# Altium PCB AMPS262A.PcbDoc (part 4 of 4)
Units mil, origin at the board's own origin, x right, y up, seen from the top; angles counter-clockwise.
Board outline 5314.96 x 4803.15 mil, 4 copper layers (Top Layer, GND, Copper Layer 3, Bottom Layer), stack 79.28 mil thick; 324 components, 156 nets, 943 pads, 1411 vias.
Unrouted connection lines stored in the file: 130.
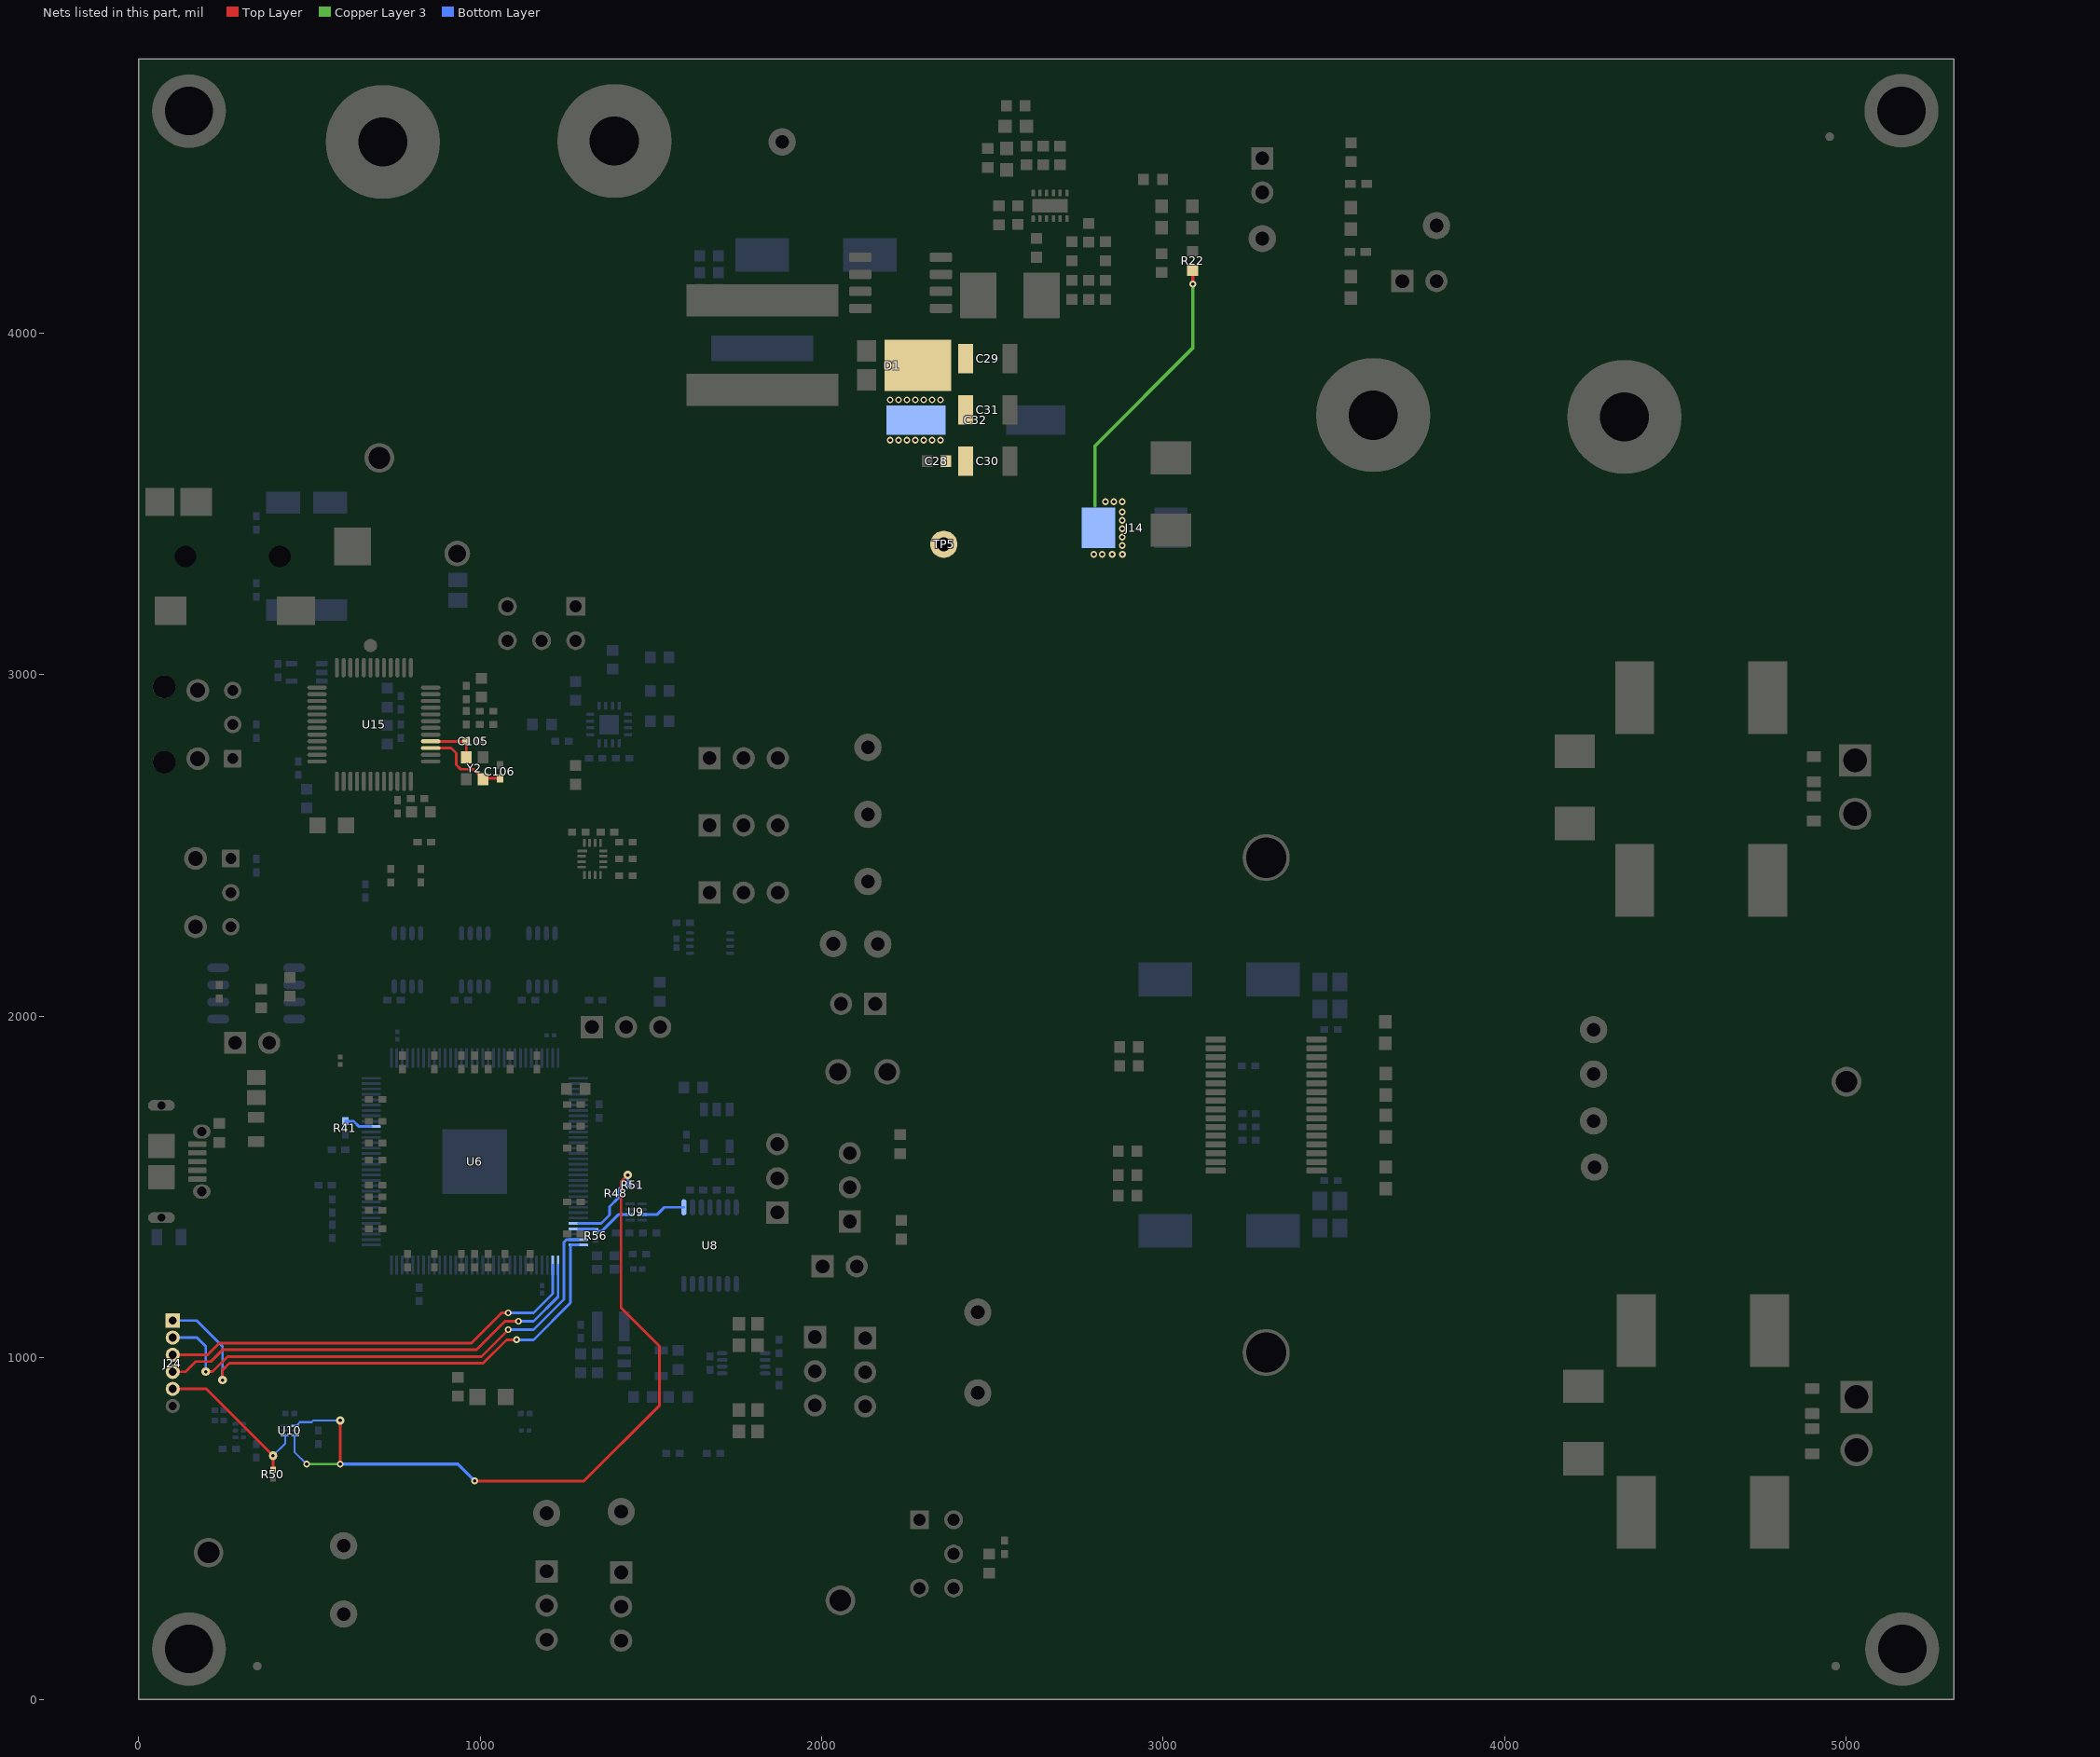
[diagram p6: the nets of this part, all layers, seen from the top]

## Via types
v1: diameter 20, hole 10, Top Layer to Bottom Layer, tented both sides, 1299 vias
v2: diameter 25, hole 10, Top Layer to Bottom Layer, tented both sides, 87 vias
v3: diameter 23.62, hole 11.81, Top Layer to Bottom Layer, 12 vias
v4: diameter 19.68, hole 7.87, Top Layer to Bottom Layer, 7 vias
v5: diameter 20, hole 10, Top Layer to Bottom Layer, 6 vias

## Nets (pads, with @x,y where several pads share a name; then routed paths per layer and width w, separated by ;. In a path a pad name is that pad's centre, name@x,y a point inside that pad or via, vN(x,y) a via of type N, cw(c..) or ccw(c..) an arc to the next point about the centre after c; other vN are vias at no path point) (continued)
VOUT_LM5155: C28.1 C29.1 C30.1 C31.1 C32.1 D1.3 J14.1 R22.2 TP5.1 | length 807.7
  Top Layer w9.84: v1(3086.32,4143.64) R22.2@3086.32,4184.09
  Copper Layer 3 w10: 2800,3495 2800,3670 3086.32,3956.32 v1(3086.32,4143.64)
  other v1: 2796.61,3352.5 2821.22,3352.5 2850.75,3352.5 2880.28,3352.5 2880,3378.29 2880,3402.89 2880,3427.5 2880,3452.11 2880,3476.71 2830.79,3506.24 2855.39,3506.24 2880,3506.24 2200.33,3686.6 2224.93,3686.6 2249.54,3686.6 2274.15,3686.6 2298.75,3686.6 2323.36,3686.6 2347.97,3686.6 2200.33,3804.71 2224.93,3804.71 2249.54,3804.71 2274.15,3804.71 2298.75,3804.71 2323.36,3804.71 2347.97,3804.71
X-24M: R56.2 U6.125 U9.2 | length 174.2
  Bottom Layer w7.87: U6.125@1287.4,1377.95 1331.89,1377.95 R56.2@1338.58,1371.26 1356.5,1371.26 1404.53,1419.29 U9.2@1438.98,1419.29
X-HS-EN: R41.1 U6.55 | length 82.3
  Bottom Layer w7.87: R41.1@605.32,1692.91 629.92,1692.91 645.67,1677.17 U6.55@681.1,1677.17
X-RSTN: R48.2 R51.2 U6.124 U10.4 U10.6 | length 2490.7
  Top Layer w7.87: v1(590.55,688.98) v2(590.55,816.93) ; v1(984.25,639.76) 1304.13,639.76 1525.59,861.22 1525.59,1033.46 1412.4,1146.65 1412.4,1515.75 v2(1432.09,1535.43)
  Copper Layer 3 w7.87: v1(492.13,688.98) v1(590.55,688.98)
  Bottom Layer w5.91: U10.6@456.3,773.62 456.3,724.8 v1(492.13,688.98) ; U10.4@461.61,801.18 472.44,812.01 506.89,812.01 511.81,816.93 v2(590.55,816.93)
  Bottom Layer w7.87: U6.124@1287.4,1393.7 1354.33,1393.7 1378.94,1418.31 1378.94,1442.91 1405.51,1469.49 1405.51,1478.15 R48.2@1408.66,1481.3 1407.48,1482.48 1407.48,1496.06 1417.32,1505.91 R51.2@1433.86,1505.91 1432.09,1507.68 v2(1432.09,1535.43)
  Bottom Layer w10: v1(590.55,688.98) 935.04,688.98 v1(984.25,639.76)
X-TCK: J24.1 U6.128 | length 1596.4
  Top Layer w7.87: v2(246.06,935.04) 246.06,964.57 265.75,984.25 1008.86,984.25 1077.76,1053.15 v1(1107.28,1053.15)
  Bottom Layer w7.87: J24.1@100,1109.25 170.28,1109.25 246.06,1033.46 v2(246.06,935.04) ; v1(1107.28,1053.15) 1156.5,1053.15 1264.76,1161.42 1264.76,1328.74 1266.73,1330.71 U6.128@1287.4,1330.71
X-TDI: J24.3 U6.2 | length 1270.3
  Top Layer w7.87: J24.3@100,1009.25 202.17,1009.25 236.22,1043.31 974.41,1043.31 1062.99,1131.89 v1(1082.68,1131.89)
  Bottom Layer w7.87: v1(1082.68,1131.89) 1156.5,1131.89 1212.6,1187.99 U6.2@1212.6,1271.65
X-TDO: J24.4 U6.1 | length 1311.9
  Top Layer w7.87: J24.4@100,959.25 137.4,959.25 167.32,989.17 211.61,989.17 246.06,1023.62 989.17,1023.62 1072.83,1107.28 v1(1112.2,1107.28)
  Bottom Layer w7.87: v1(1112.2,1107.28) 1156.5,1107.28 1228.35,1179.13 U6.1@1228.35,1271.65
X-TMS: J24.2 U6.127 | length 1535.1
  Top Layer w7.87: v2(196.85,959.65) 216.54,959.65 260.83,1003.94 1003.94,1003.94 v1(1082.68,1082.68)
  Bottom Layer w7.87: J24.2@100,1059.25 171.06,1059.25 196.85,1033.46 v2(196.85,959.65) v2@196.85,954.72 ; v1(1082.68,1082.68) 1156.5,1082.68 1245.08,1171.26 1245.08,1338.58 1252.95,1346.46 U6.127@1287.4,1346.46
X-TRSTN: J24.5 R50.2 U10.1 | length 563.9
  Top Layer w7.87: J24.5@100,909.25 198.03,909.25 v2(393.7,713.58) R50.2@393.7,674.21
  Bottom Layer w5.91: 429.53,749.41 v2(393.7,713.58) 429.53,749.41 ; 429.53,749.41 429.53,773.62 429.53,749.41
XIN/CLK: U8.1 U9.7 | length 131
  Bottom Layer w7.87: U9.7@1474.41,1419.29 1517.72,1419.29 1539.37,1440.94 U8.1@1596.46,1440.94
XTI: C106.1 U15.39 Y2.1 | length 262.6
  Top Layer w7.87: U15.39@855.32,2785.43 915.35,2785.43 930.12,2770.67 930.12,2736.22 942.91,2723.43 980.29,2723.43 1008.86,2694.85 Y2.1@1008.86,2693.9 1011.81,2696.85 C106.1@1058.07,2696.85
XTO: C105.1 U15.40 Y2.3 | length 150.6
  Top Layer w7.87: U15.40@855.32,2805.12 C105.1@959.65,2805.12 Y2.3@959.65,2758.86
pads on no net: FID1.1 FID2.1 FID3.1 FID4.1 FID5.1 FID6.1 H2. H3. H4. H5. J30.MH1 J30.MH2 R73.2 R74.2 S1.1 S1.3 S1.6 S2.1 S2.3 SH-J1.0 SH-J2.0 SH-J3.0 SH-J4.0 SH-J5.0 SH-J6.0 SH-J7.0 SH-J8.0 SH-J9.0 SH-J10.0 U3.7 U6.4 U6.5 U6.7 U6.8 U6.9 U6.10 U6.12 U6.15 U6.18 U6.20 U6.21 U6.22 U6.23 U6.25 U6.26 U6.28 U6.30 U6.31 U6.32 U6.33 U6.34 U6.35 U6.39 U6.40 U6.50 U6.51 U6.53 U6.54 U6.57 U6.58 U6.59 U6.61 U6.62 U6.65 U6.68 U6.69 U6.70 U6.71 U6.72 U6.74 U6.75 U6.76 U6.77 U6.79 U6.82 U6.84 U6.85 U6.86 U6.89 U6.90 U6.91 U6.93 U6.94 U6.95 U6.96 U6.97 U6.98 U6.99 U6.100 U6.106 U6.107 U6.108 U6.109 U6.112 U6.113 U6.114 U6.115 U6.117 U6.118 U6.119 U6.121 U6.122 U8.4 U8.8 U8.14 U9.6 U12. U12.4 U12.5 U14.4 U14.5 U15.2 U15.3 U15.4 U15.5 U15.6 U15.11 U15.12 U15.13 U15.14 U15.16 U15.28 U15.29 U15.30 U15.31 U15.32 U15.35 U15.37 U16.3 U17.3 U18.1 U19.3 U20.2 U20.3 U21.4 U21.11 U21.17@1377.95,2854.33
copper on no net:
  other v1: 1421,1590.19

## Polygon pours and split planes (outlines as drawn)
VOUT_LM5155 on Copper Layer 3 "COPPER_LAYER_3_VOUT_LM5155_P083" (solid, remove dead copper, pour order 83): 2180.64,3833.86 2356.14,3833.86 2375,3815 2375,3535 2395,3525 2885,3525 2910,3500 2910,3334.55 2310,3334.55 2180,3407.5 2180.64,3165.64 2180,3834.5
GND on Copper Layer 3 "COPPER_LAYER_3_GND_P133" (solid, remove dead copper, pour order 133): 0,4305.65 494.35,4800 4647.5,4800 5315,4132.5 5315,510 5307.5,510 4800,2.5 512.5,2.5 512.5,12.5 210,315 0,315 0,4302.5 -2.5,4305
5V-U3 on Copper Layer 3 "COPPER_LAYER_3_5V-U3_P000" (solid, remove dead copper, pour order 0): 187.01,2155.51 147.64,2116.14 147.64,1865.16 310.87,1865.16 322.5,1883.55 322.5,2118.44 285.43,2155.51
PVDD_5828 on Copper Layer 3 "COPPER_LAYER_3_PVDD_5828_P085" (solid, remove dead copper, pour order 85): 3452.5,2787.5 2940,3222.5 2940,3365 3100,3365 3623.38,2922.41 3623.38,2821.1
VIN on Copper Layer 3 "Copper Layer 3-VIN" (solid, pour order 77): 1606.19,4745 1960.59,4745 2015,4690.59 2014.37,4689.96 2014.37,4279.37 2000,4265 1630,4265 1606.19,4288.81
PVDD_5828 on Copper Layer 3 "COPPER_LAYER_3_PVDD_5828_P064" (solid, remove dead copper, pour order 64): 3451.28,2821.1 3451.28,2488.63 3181.28,2218.63 3181.28,2052.1 3317.28,1916.1 3317.28,1548.56 3181.28,1412.56 3181.28,1295.56 3197.28,1279.56 3567.85,1279.56 3587.77,1299.48 3587.77,2247.64 3623.38,2283.25 3623.38,2821.1
3.3V on Copper Layer 3 "COPPER_LAYER_3_3.3V_P004" (solid, remove dead copper, pour order 4): 831.69,1825.79 639.76,2017.72 639.76,2312.99 984.25,2657.48 984.25,3041.34 964.57,3061.02 964.57,3179.13 944.88,3198.82 925.2,3198.82 905.51,3179.13 905.51,3061.02 885.83,3041.34 836.61,3041.34 836.61,2908.46 733.27,2805.12 733.27,2750.98 472.44,2490.16 472.44,2249.02 388.78,2165.35 388.78,2071.85 723.42,1737.2 831.69,1737.2
1.0V on Copper Layer 3 "COPPER_LAYER_3_1.0V_P063" (solid, remove dead copper, pour order 63): 1264.76,1072.83 1240.16,1072.83 1220.47,1053.15 1220.47,1018.7 1250,989.17 1269.68,989.17 1279.53,999.02 1279.53,1058.07
3.3V on Copper Layer 3 "COPPER_LAYER_3_3.3V_P002" (solid, pour order 2): 1259.84,1820.87 1240.16,1840.55 718.5,1840.55 718.5,1368.11 787.4,1299.21 1200.79,1299.21 1259.84,1358.27
GND on Top Layer "TOP_LAYER_GND_P129" (solid, remove dead copper, pour order 129): 0,4308.5 2.66,4308.5 499.15,4805 4641.85,4803.15 4860,4585 5314.96,4130.04 5314.96,517.46 4797.5,0 497.64,0 497.64,22.36 205,315 0,315
5V-U3 on Top Layer "TOP_LAYER_5V-U3_P121" (solid, remove dead copper, pour order 121): 372.5,1797.5 372.5,1855 347.5,1855 322.85,1879.65 322.85,1962.85 173.44,1962.85 147.64,1937.06 147.64,1862.36 212.5,1797.5
Left+ on Top Layer "TOP_LAYER_LEFT+_P113" (solid, remove dead copper, pour order 113): 4717.5,441.02 4902.5,441.02 5097.5,636.02 5097.5,788.52 4992.5,788.52 4945,741.02 4805,741.02 4717.5,653.52
Left- on Top Layer "TOP_LAYER_LEFT-_P111" (solid, remove dead copper, pour order 111): 4717.5,1186.02 4905,1186.02 5097.5,993.52 5097.5,833.52 5087.5,823.52 4975.3,823.52 4910.3,888.52 4802.5,888.52 4717.5,973.52
Right- on Top Layer "TOP_LAYER_RIGHT-_P109" (solid, remove dead copper, pour order 109): 4712.5,2291.02 4910,2291.02 4910,2298.52 5087.5,2476.02 5087.36,2476.16 5087.36,2646.02 5000,2646.02 4945,2591.02 4800,2591.02 4712.5,2503.52
Right+ on Top Layer "TOP_LAYER_RIGHT+_P107" (solid, remove dead copper, pour order 107): 4712.5,3038.52 4910,3038.52 5087.36,2861.16 5087.36,2696.02 4972.5,2696.02 4927.5,2741.02 4787.5,2741.02 4712.5,2816.02
OUT_A+ on Top Layer "TOP_LAYER_OUT_A+_P105" (solid, remove dead copper, pour order 105): 3449,1607.5 3522.5,1607.5 3615.62,1514.38 3685.62,1514.38 3745,1455 3745,825 3812.5,757.5 4350,757.5 4442.5,650 4442.5,442.5 4350,390 4165,390 3847.5,390 3602.5,635 3602.5,1440 3512.5,1530 3512.5,1562.5 3485,1590 3449,1590
OUT_A- on Top Layer "TOP_LAYER_OUT_A-_P097" (solid, remove dead copper, pour order 97): 3467.5,1710 3590.65,1710 3630.65,1670 3850,1670 3907.5,1612.5 3907.5,1320 3985,1242.5 4345,1242.5 4440,1187.5 4440,970 4323.2,863 3859.5,863 3815,907.5 3815,1557.5 3742.5,1630 3607.5,1630 3545,1692.5 3467.5,1692.5
OUT_B- on Top Layer "TOP_LAYER_OUT_B-_P095" (solid, remove dead copper, pour order 95): 3465,1787.5 3537.5,1787.5 3600,1850 3697.5,1850 3812.5,1965 3812.5,2520 3910,2617.5 4358.94,2617.5 4437,2505.5 4437,2291.73 4345,2199.72 4004.72,2199.72 3910,2105 3910,1882.67 3834.83,1807.5 3620,1807.5 3582.5,1770 3465,1770
OUT_B+ on Top Layer "TOP_LAYER_OUT_B+_P093" (solid, remove dead copper, pour order 93): 3449,1889.68 3484.69,1889.68 3500,1905 3500,1929.9 3602.5,2032.4 3600,2034.9 3600,2840 3882.5,3122.5 4345,3122.5 4437.5,3037.5 4437.5,2827.5 4353.04,2722.5 3802.5,2722.5 3745,2665 3745,2025 3685,1965 3620.07,1965 3527.57,1872.5 3449,1872.5
BIAS on Top Layer "TOP_LAYER_BIAS_P052" (solid, remove dead copper, pour order 52): 2495.17,4340.65 2490.17,4335.65 2490.17,4270.65 2495.17,4265.65 2587.67,4265.65 2595.17,4273.15 2595.17,4290.65 2625.17,4320.65 2640.17,4320.65 2645.17,4325.65 2645.17,4345.65 2595.17,4345.65 2590.17,4340.65
GND-USB on Top Layer "TOP_LAYER_GND-USB_P008" (solid, pour order 8): 139.76,1531.99 139.76,1463.09 153.54,1449.31 173.23,1449.31 187.01,1463.09 187.01,1509.35 192.91,1515.26 192.91,1531.99
5V-SPDIF on Top Layer "TOP_LAYER_5V-SPDIF_P062" (solid, remove dead copper, pour order 62): 314.96,1786.42 314.96,1692.91 319.88,1687.99 369.09,1687.99 374.02,1692.91 374.02,1786.42
1.0V on Top Layer "TOP_LAYER_1.0V_P036" (solid, pour order 36): 797.24,1825.79 733.27,1761.81 733.27,1373.03 782.48,1323.82 1107.28,1323.82 1235.24,1451.77 1235.24,1747.05 1156.5,1825.79
1.0V on Top Layer "TOP_LAYER_1.0V_P018" (solid, pour order 18): 1279.53,1328.74 1269.68,1338.58 1269.68,1397.64 1205.71,1461.61 1131.89,1387.8 1176.18,1343.5 1176.18,1028.54 1210.63,994.09 1264.76,994.09 1279.53,1008.86
3.3V on Top Layer "TOP_LAYER_3.3V_P016" (solid, remove dead copper, pour order 16): 408.46,2185.04 383.89,2160.46 383.89,2111.19 398.62,2096.46 467.52,2096.46 487.2,2076.77 501.97,2076.77 511.81,2086.61 511.81,2145.67 472.44,2185.04
VBUS_IN on Top Layer "TOP_LAYER_VBUS_IN_P014" (solid, remove dead copper, pour order 14): 206.69,1614.17 369.09,1614.17 369.09,1648.62 196.85,1648.62 185.04,1636.81 145.67,1636.81 145.67,1617.13 203.74,1617.13
5V-U3 on Top Layer "TOP_LAYER_5V-U3_P012" (solid, remove dead copper, pour order 12): 187.01,2155.51 285.43,2155.51 295.28,2145.67 295.28,2086.61 285.43,2076.77 187.01,2076.77 177.17,2086.61 177.17,2145.67
GND on Bottom Layer "BOTTOM_LAYER_GND_P135" (solid, remove dead copper, pour order 135): -2.5,4302.5 492.5,4797.5 4650,4797.5 4652.5,4800 5305,4147.5 5305,512.5 5307.5,510 4797.5,0 516.89,0 210,306.89 210,307.5 7.5,307.5 -5,320 -5,4302.5
3.3V-TP on Bottom Layer "BOTTOM_LAYER_3.3V-TP_P022" (solid, remove dead copper, pour order 22): 885.83,3366.14 885.83,3375.83 910,3400 960,3400 984.25,3375.75 984.25,3366.14 984.25,3272.64 964.57,3252.95 905.51,3252.95 885.83,3272.64
1.0V on Bottom Layer "BOTTOM_LAYER_1.0V_P034" (solid, remove dead copper, pour order 34): 1220.47,1018.7 1245.08,994.09 1358.27,994.09 1363.19,999.02 1363.19,1131.89 1358.27,1136.81 1328.74,1136.81 1328.74,1082.68 1318.9,1072.83 1240.16,1072.83 1220.47,1053.15
3.3V on Bottom Layer "BOTTOM_LAYER_3.3V_P032" (solid, remove dead copper, pour order 32): 1510.83,1008.86 1515.75,1003.94 1594.49,1003.94 1604.33,1013.78 1604.33,1058.07 1594.49,1067.91 1545.28,1067.91 1510.83,1033.46
SW on Bottom Layer "BOTTOM_LAYER_SW_P030" (solid, remove dead copper, pour order 30): 1402.56,1008.86 1402.56,1131.89 1407.48,1136.81 1437.01,1136.81 1441.93,1131.89 1441.93,1008.86
3.3V on Bottom Layer "BOTTOM_LAYER_3.3V_P028" (solid, remove dead copper, pour order 28): 418.31,2076.77 388.78,2106.3 388.78,2165.35 408.46,2185.04 472.44,2185.04 511.81,2145.67 511.81,2086.61 501.97,2076.77
5V-U3 on Bottom Layer "BOTTOM_LAYER_5V-U3_P026" (solid, remove dead copper, pour order 26): 187.01,2155.51 285.43,2155.51 295.28,2145.67 295.28,2086.61 285.43,2076.77 187.01,2076.77 177.17,2086.61 177.17,2145.67
3.3V on Bottom Layer "BOTTOM_LAYER_3.3V_P024" (solid, remove dead copper, pour order 24): 905.51,3243.11 905.51,3154.53 915.35,3144.69 954.72,3144.69 964.57,3154.53 964.57,3243.11
GND on GND "GND_GND_P131" (solid, remove dead copper, pour order 131): 0,4307.5 495,4802.5 4642.5,4802.5 5315,4130 5315,515 5312.5,515 4797.5,0 515,0 515,6.69 206.69,315 0,315

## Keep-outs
Keep-Out Layer:
  text ".Layer_Name" at 577,-858.49 h60

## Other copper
Top Layer:
  region net GND: 3418.5,1641.73 3418.5,1684.95 3477.34,1684.95 3493.93,1668.36 3536.5,1668.36 3541.5,1663.36 3541.5,1643.36 3536.5,1638.36 3484.02,1638.36 3480.65,1641.73
  region net GND: 3178.94,1513.9 3184.94,1519.9 3184.94,1556.9 3122.5,1556.9 3122.5,1519.9 3128.5,1513.9
  region net GND: 3178.94,1966.36 3184.94,1960.36 3184.94,1923.36 3122.5,1923.36 3122.5,1960.36 3128.5,1966.36
  region net GND: 3418.5,1838.53 3418.5,1795.31 3477.34,1795.31 3519.91,1795.31 3541.5,1816.9 3541.5,1836.9 3536.5,1841.9 3484.02,1841.9 3480.65,1838.53
  region net PVDD-EXT: 3750,3545 3822.29,3617.29 3822.29,3920 3188.32,3920 3049.33,3781.01 3027.02,3758.7 3003.32,3735 2944.55,3735 2912.5,3714.51 2912.5,3644.18 2912.5,3545
  pour cut-out: 3633.2,1745 3678.84,1745 3678.84,1738.61 3673.61,1733.38 3642.97,1733.38 3642.97,1735.23
  pour cut-out: 3635.23,1684.77 3678.84,1684.77 3678.84,1676.34 3675.65,1673.15 3645,1673.15 3645,1675
  pour cut-out: 3618.8,1535.92 3618.8,1520 3678.81,1520 3678.81,1540.92 3623.8,1540.92
  pour cut-out: 3627.5,1965 3627.5,1938.16 3677.5,1938.16 3677.5,1965
  region net GND: 2827.5,1841.23 2841.53,1827.2 2882.53,1827.2 2891.53,1836.2 2891.53,1929.2 2882.53,1938.2 2841.53,1938.2 2827.5,1924.17
  region net GND: 2830.47,1456.09 2838.47,1448.09 2879.47,1448.09 2888.47,1457.09 2888.47,1550.09 2879.47,1559.09 2838.47,1559.09 2830.47,1551.09
  region net GND: 2886,1574.39 2891,1579.39 2891,1630.39 2884,1637.39 2846.58,1637.39 2842.64,1633.45 2842.64,1574.39
  region net PVDD_5828: 3376.5,1582.36 3477.5,1582.36 3484.5,1575.36 3484.5,1319.36 3452.5,1287.36 3230.5,1287.36 3214.5,1303.36 3214.5,1420.36
  region net PVDD_5828: 3376.5,1897.9 3477.5,1897.9 3484.5,1904.9 3484.5,2160.9 3452.5,2192.9 3230.5,2192.9 3214.5,2176.9 3214.5,2059.9
  region net PVDD_5828: 2952.5,3475.16 2952.5,3235.16 2962.5,3225.16 3082.5,3225.16 3092.5,3235.16 3092.5,3475.16
  region net BIAS: 1600.17,3885.65 1600.17,3780.65 1630.17,3750.65 2022.45,3750.65 2052.45,3780.65 2052.45,3885.65
  region net VIN: 1665,4290.65 1673.92,4325 1673.92,4745.65 1607.73,4745.65 1463.28,4745.65 1322.73,4745.65 1178.28,4745.65 1138.28,4705.65 1138.28,4310.65 1158.28,4290.65
  region net Q1-S: 2515.17,4180.65 2500.17,4195.65 2310.17,4195.65 2300.17,4185.65 2300.17,4060.65 2300.17,4015.65 2305.17,4010.65 2495.17,4010.65 2515.17,4030.65
  region net Q1-D: 2280.17,4245.65 2240.17,4285.65 2070.17,4285.65 1955.17,4170.65 1625.17,4170.65 1590.17,4135.65 1590.17,4025.65 1605.17,4010.65 2060.17,4010.65 2100.17,3970.65 2100.17,3830.65 2105.17,3825.65 2155.17,3825.65 2160.17,3830.65 2160.17,3990.65 2200.17,4030.65 2260.17,4030.65 2280.17,4050.65
  region net VOUT_LM5155: 2465.17,3575.65 2465.17,3965.65 2440.17,3990.65 2190.17,3990.65 2180.64,3981.12 2180.64,3686.6 2195.41,3671.83 2318.99,3671.83 2345.17,3645.65 2345.17,3590.65 2365.17,3570.65 2370.17,3565.65 2455.17,3565.65
  text ".Layer_Name" at 577,-858.49 h60
Copper Layer 3:
  region net BIAS: 2595.17,4273.15 2595.17,4335.65 2590.17,4340.65 2495.17,4340.65 2490.17,4335.65 2490.17,4270.65 2497.17,4263.65 2585.67,4263.65
  region net BIAS: 2022.45,3750.65 1696.17,3750.65 1690.17,3756.65 1690.17,3799.65 1775.17,3884.65 2051.45,3884.65 2052.45,3885.65 2052.45,3780.65
  region net PVDD-EXT: 3280,3620 3345,3555 3760,3555 3825,3620 3825,3855 3775,3905 3555,3905 3475,3825 3280,3825
Bottom Layer:
  rectangle net VOUT_LM5155: 2781.75,3327.5 2912.5,3527.5
  region net PVDD_5828: 3214.5,1303.36 3230.5,1287.36 3452.5,1287.36 3484.5,1319.36 3484.5,1529.36 3482.98,1530.87 3484.5,1532.39 3484.5,2160.9 3452.5,2192.9 3230.5,2192.9 3214.5,2176.9 3214.5,1992.31 3350.98,1855.83 3350.98,1556.84 3214.5,1420.36
  region net PVDD-EXT: 3280,3620 3346.22,3553.78 3760,3553.78 3825,3618.78 3825,3855 3760,3920 3345,3920 3280,3855
  region net PVDD_5828: 2952.5,3475.16 2952.5,3235.16 2962.5,3225.16 3082.5,3225.16 3092.5,3235.16 3092.5,3475.16
  region net BIAS: 1795.17,3885.65 1672.45,3885.65 1657.45,3870.65 1657.45,3765.65 1672.45,3750.65 1826.31,3750.65 1980.17,3750.65 1995.17,3765.65 1995.17,3870.65 1980.17,3885.65 1857.45,3885.65
  region net VIN: 1780,4660 1680.17,4430.65 1680.17,4060.65 1670.17,4050.65 1670.17,3920.65 1680.17,3910.65 1975.17,3910.65 1985.17,3920.65 1985.17,4100.65 1985.17,4530.65 1985.17,4660
  region net VIN: 1627.73,4290.65 1647.73,4310.65 1647.73,4705.65 1607.73,4745.65 1463.28,4745.65 1322.73,4745.65 1178.28,4745.65 1138.28,4705.65 1138.28,4310.65 1158.28,4290.65
  region net GND: 1660.17,4115.65 1670.17,4105.65 1670.17,4080.65 1665.17,4075.65 1600.17,4075.65 1590.17,4085.65 1590.17,4250 1605.17,4265 1660.17,4265
  region net VOUT_LM5155: 2367.65,3804.71 2352.89,3819.47 2195.41,3819.47 2180.64,3804.71 2180.64,3686.6 2195.41,3671.83 2352.89,3671.83 2367.65,3686.6
  text ".Layer_Name" at 577,-858.49 h60

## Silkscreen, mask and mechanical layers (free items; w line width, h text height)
Top Overlay:
  lines w10: 1033.46,200 1072.83,200 ; 1033.46,330 1072.83,330 ; 1120,142 1072.83,142 1072.83,255 1120,255 ; 1120,272 1072.83,272 1072.83,385 1120,385 ; 1477.83,142 1525,142 1525,255 1477.83,255 ; 1477.83,272 1525,272 1525,385 1477.83,385 ; 1525,200 1564.37,200 ; 1525,330 1564.37,330
  text "VIN" at 1830,4650 h60
  text "TAS5830EVM" at 4105,4410 h70
  text "GND" at 3732.5,4385 h60
  text "'.PRJ_Number'.PCB_Rev" at 4165.5,4306 h70
  text "GND" at 630,4245 h60
  text "BATTERY" at 1155,4215 h60
  text "GND" at 785.83,3695 h49.21
  text "3.3V" at 1016,3413 h49.21
  text "PVDD-EXT" at 3390,3365 h80
  text "GND" at 4125,3365 h80
  text "VOUT" at 2274.15,3257.5 h60
  text "SPDIF" at 854,3202 h49.21
  text "XMOS" at 1348.43,3142.36 h49.21
  text "BYPASS PSIA" at 1535,2858 h49.21
  text "-" at 4991,2830.36 h60
  text "OPTO" at 40,2582.5 h60
  text "OUT" at 282.5,2582.5 h60
  text "+" at 4993,2450.36 h60
  text "SPDIF" at 494.91,2444.24 h50
  text "LOCK" at 503.56,2372.14 h50
  text "OPTO" at 412.23,2267.35 h60
  text "GPIO2" at 1805,2212.5 h39.37
  text "PDN" at 2235,2194.88 h39.37
  text "IN" at 427.61,2177.95 h60
  text "WARN" at 1800,2150 h39.37
  text "PD_DET_PDN" at 1651,2021 h39.37
  text "OUT_B/Right" at 5235.65,1966.45 h60 r90
  text "GND" at 450,1905 h47.24
  text "5V" at 117.5,1890.19 h60
  text "XMOS" at 1277,1851 h39.37
  text "SPDIF" at 1488,1851 h39.37
  text "GND" at 4931,1657.36 h60
  text "3.3V" at 1639,1603 h49.21
  text "SW" at 2192.5,1572.5 h39.37 r90
  text "ADR" at 2015,1470 h40 r90
  text "1.8V" at 1659,1379 h49.21
  text "HW" at 2191.86,1368.11 h39.37 r90
  text "DVDD1" at 1746,1251 h49
  text "GPIO1" at 2255.17,1100 h39.37
  text "Hybrid_Pro" at 2260,1022.5 h39.37
  text "OUT_A/Left" at 5240,976.02 h60 r90
  text "-" at 4997.5,951.97 h60
  text "USB" at 1137.5,945 h60
  text "GPIO0" at 2241.61,895 h39.37
  text "READY" at 1140,847.5 h60
  text "FAULT" at 2240,825 h39.37
  text "+" at 4995,588.52 h60
  text "PDN=HIGH" at 2215,585 h31.5
  text "GND" at 143,521 h60
  text "INTERNAL" at 785,320 h31.5
  text "INTERNAL" at 1582,320 h31.5
  text "PDN=LOW" at 2220,230 h31.5
  text "EXTERNAL" at 782.72,185 h31.5
  text "EXTERNAL" at 1579.72,185 h31.5
  text "GND" at 1978,130 h60
  text "GND" at 1144.88,75 h37
  text "GND" at 1365,72.5 h37
  text ".Layer_Name" at 577,-858.49 h60
Bottom Overlay:
  text ".Layer_Name" at 577,-858.49 h39.37
Top Paste:
  text ".Layer_Name" at 577,-858.49 h60
Bottom Paste:
  text ".Layer_Name" at 577,-858.49 h60
Top Solder:
  text ".Layer_Name" at 577,-858.49 h60
  text ".Layer_Name" at 577,-858.49 h60
Bottom Solder:
  text ".Layer_Name" at 577,-858.49 h60
Drill Guide:
  text ".Layer_Name" at 577,-858.49 h60
M1 Board Outline:
  the board outline again, w20
  text ".Layer_Name" at 577,-858.49 h60
M2 Board Dimensions:
  rectangle: 0,-275 125,-150
  rectangle: 125,-400 500,-275
  lines w7: 0,-275 1000,-275 ; 125,-400 125,-150 ; 250,-400 250,-150 ; 500,-400 500,-150 ; 750,-400 750,-150 ; 0,-400 1000,-400 1000,-150 0,-150 0,-400
  text ".Layer_Name" at 577,-858.49 h60
M3 3D STEP Top:
  text ".Layer_Name" at 577,-858.49 h60
M4 3D STEP Bottom:
  text ".Layer_Name" at 577,-858.49 h60
Top M5 Assembly Top/M6 Assembly Bottom:
  lines w10: -292,-930.17 6308,-930.17 ; -292,-726.83 6310,-726.83 ; -292,-523.5 -292,-1133.5 3713,-1133.5 6310,-1133.5 6310,-523.5 -291.5,-523.5 -291.5,-1133.5 1284,-1133.5 ; 2173,-1133.5 2173,-523.5 ; 3440,-726.83 3440,-523.5 ; 4280,-726.83 4280,-523.5 ; 4902,-1140 4902,-937.17
  text "COMPONENTS MARKED 'DNP' SHOULD NOT BE POPULATED." at 1153.5,-318.5 h60
  text "ASSEMBLY VARIANT:" at 1153,-434 h60
  text ".VariantName" at 2189,-434 h60
  text "PCB VIEWED FROM TOP SIDE" at -228.5,-655.67 h60
  text "BOARD #:" at 2248,-655.67 h60
  text ".PRJ_Number" at 2793.5,-655.67 h60
  text "REV:" at 3638,-655.67 h60
  text ".PCB_Rev" at 3929.5,-655.67 h60
  text "SVN REV:" at 4476,-655.67 h60
  text ".VersionControl_RevNumber" at 4982,-655.67 h60
  text "TID #:" at 2248,-859 h60
  text ".TID" at 2793.5,-859 h60
  text "PLOT NAME =" at -228.5,-1064.34 h60
  text ".plot_File_Name" at 577,-1064.34 h60
  text "GENERATED    :" at 2250,-1064.34 h60
  text ".Print_Date" at 3119.5,-1064.34 h60
  text ".Print_Time" at 3848.5,-1064.34 h60
  text "TEXAS INSTRUMENTS" at 5113,-1064.34 h60
Bottom M5 Assembly Top/M6 Assembly Bottom:
  lines w10: -292.5,-727.33 6309.5,-727.33 ; -290.5,-930.67 6309.5,-930.67 ; 1115.5,-1140.5 1115.5,-937.67 ; 1737.5,-727.33 1737.5,-524 ; 2577.5,-727.33 2577.5,-524 ; 3844.5,-1134 3844.5,-524 ; 4733.5,-1134 6309,-1134 6309,-524 -292.5,-524 -292.5,-1134 2304.5,-1134 6309.5,-1134 6309.5,-524
  text "COMPONENTS MARKED 'DNP' SHOULD NOT BE POPULATED." at 6102,-318 h60
  text ".VariantName" at 5058,-434 h60
  text "ASSEMBLY VARIANT:" at 6097,-434 h60
  text ".VersionControl_RevNumber" at 1035.5,-656.17 h60
  text "SVN REV:" at 1541.5,-656.17 h60
  text ".PCB_Rev" at 2088,-656.17 h60
  text "REV:" at 2379.5,-656.17 h60
  text ".PRJ_Number" at 3224,-656.17 h60
  text "BOARD #:" at 3769.5,-656.17 h60
  text "PCB VIEWED FROM BOTTOM SIDE" at 6246,-656.17 h60
  text ".TID" at 3224,-859.5 h60
  text "TID #:" at 3769.5,-859.5 h60
  text "TEXAS INSTRUMENTS" at 904.5,-1064.84 h60
  text ".Print_Time" at 2169,-1064.84 h60
  text ".Print_Date" at 2898,-1064.84 h60
  text "GENERATED    :" at 3767.5,-1064.84 h60
  text ".plot_File_Name" at 5440.5,-1064.84 h60
  text "PLOT NAME =" at 6246,-1064.84 h60
M9 Title Sheet:
  drawing of 57 lines, arcs and shapes, not listed
  text "1" at 739.84,8036.5 h70
  text "2" at 3235.5,8036.5 h70
  text "3" at 5724.84,8036.5 h70
  text "4" at 8231.51,8036.5 h70
  text "5" at 10730.5,8036.5 h70
  text "6" at 13235.5,8036.5 h70
  text "A" at -416.5,6893.5 h70
  text "A" at 14383.5,6893.5 h70
  text "B" at -416.5,4513.5 h70
  text "B" at 14383.5,4513.5 h70
  text "C" at -416.5,2138.5 h70
  text "C" at 14383.5,2138.5 h70
  text "PROJECT TITLE:" at 11343.5,277.5 h45
  text ".PRJ_Title" at 11393.5,144.17 h70
  text "DESIGNED FOR:" at 11343.5,-23.5 h45
  text ".PRJ_Customer" at 11393.5,-163.5 h70
  text "D" at -416.5,-231.5 h70
  text "D" at 14383.5,-231.5 h70
  text "FILE NAME:" at 11343.5,-323.5 h45
  text ".PCB_File_Name_No_Path" at 11393.5,-443.5 h70
  text "Texas Instruments (TI) and/or its licensors do not warrant the accuracy or completeness of this specification" at 6374,-605.34 h45
  text "ENGINEER:" at 11343.5,-613.5 h45
  text "LAYOUT BY:" at 12848.5,-613.5 h45
  text "or any information contained therein. TI and/or its licensors do not warrant that this design will meet" at 6329.01,-718 h45
  text ".PRJ_Engineer" at 11393.5,-768.49 h70
  text ".PCB_Layout" at 12899,-768.49 h70
  text "the specifications, will be suitable for your application or fit for any particular purpose, or will operate in" at 6329.01,-830.67 h45
  text ".Layer_Name" at 577,-858.49 h60
  text "ALTIUM DESIGNER VERSION:" at 12848.5,-923.5 h45
  text "an implementation. TI and/or its licensors do not warrant that the design is production worthy. You should" at 6329.01,-943.33 h45
  text "completely validate and test your design implementation to confirm the system functionality for your application." at 6374,-1056 h45
  text ".print_Scale" at 11393.5,-1056.83 h70
  text ".Application_BuildNumber" at 12899,-1056.83 h70
  text "1" at 739.84,-1263.5 h70
  text "2" at 3235.5,-1263.5 h70
  text "3" at 5724.84,-1263.5 h70
  text "4" at 8231.51,-1263.5 h70
  text "5" at 10730.5,-1263.5 h70
  text "6" at 13235.5,-1263.5 h70
M10 Fab Notes:
  drawing of 189 lines, arcs and shapes, not listed
  text "DESIGN INFORMATION" at 12382.02,6356.17 h60
  text "MIN. TRACK WIDTH:" at 11737.46,6224.05 h60
  text "8" at 12833.7,6224.05 h60
  text "MIL" at 12988.46,6224.05 h60
  text "MIN. CLEARANCE:" at 11737.46,6099.92 h60
  text "0.2" at 12773.7,6099.93 h60
  text "mm" at 12988.46,6099.92 h60
  text "MIN. VIA PAD SIZE:" at 11737.46,5975.8 h60
  text "20" at 12803.71,5975.8 h60
  text "MIL" at 12988.46,5975.8 h60
  text "0.05mm (2MIL)" at 12432.46,5845.9 h60
  text "MINIMUM ANNULAR RING" at 11408.23,5837.67 h60
  text "EXTERNAL" at 13140.46,5837.67 h60
  text "PER" at 11608.23,5727.55 h60
  text "IPC-D-275 CLASS 2 LEVEL C" at 11828.23,5727.54 h60
  text "MIL, HOLES" at 13316.46,5627.07 h60
  text "+/-" at 12924,5618.48 h60
  text "+/-" at 13778,5618.48 h60
  text "REGISTRATION TOLERANCES:" at 11408.23,5617.42 h60
  text "METAL" at 12608,5617.42 h60
  text "5" at 13184.2,5617.42 h60
  text "3" at 14017.2,5617.42 h60
  text "MIL" at 14133.46,5617.42 h60
  text "HOLE SIZE TOLERANCE (UNLESS OTHERWISE SPECIFIED):" at 11408.23,5519.1 h60
  text "+/-" at 13778,5516.23 h60
  text "3" at 14017.2,5515.17 h60
  text "MIL" at 14133.46,5515.17 h60
  text "MATERIAL:" at 11333.46,5377.52 h60
  text "FR-4 High Tg" at 12319.9,5249 h60
  text "X" at 12175.46,5241.01 h60
  text "FR-408" at 11754.46,5236.49 h60
  text "OTHER" at 13242.46,5236.49 h60
  text "80 MIL (2.0mm) +/-10%" at 12074.56,5093.46 h60
  text "X" at 11954.46,5091.01 h60
  text "THICKNESS:" at 11408.23,5085.24 h60
  text "OTHER" at 13359.46,5085.24 h60
  text "TOLERANCE:" at 11408.23,4946.92 h60
  text "X" at 12256.46,4946.92 h60
  text "ANSI IPC-6012 TYPE 3 CLASS 2" at 12434.48,4946.92 h60
  text "OTHER +/-" at 12434.46,4802.73 h60
  text "BOW & TWIST:" at 11408.23,4657.54 h60
  text "X" at 12256.46,4657.54 h60
  text "ANSI IPC-6012 TYPE 3 CLASS 2" at 12434.48,4657.54 h60
  text "OTHER +/-" at 12434.46,4510.85 h60
  text "DRILLING:" at 11333.46,4380.23 h60
  text "NC_DRILL FILES" at 13094.46,4275.04 h60
  text "REFERENCE:" at 11408.23,4271.1 h60
  text "X" at 12065.46,4271.01 h60
  text "AS SHOWN" at 12243.46,4271.1 h60
  text "X" at 12966.46,4271.1 h60
  text "OTHER" at 13392.46,4128.85 h60
  text "PTH COPPER THICKNESS:" at 11407.91,4125.32 h60
  text "X" at 12547.14,4125.32 h60
  text "20-30 um" at 12675.14,4125.32 h60
  text "BOARD FINISH:" at 11333.46,3977.73 h60
  text "SILKSCREEN:" at 11488.68,3867.6 h60
  text "X" at 12446.46,3867.6 h60
  text "TOP" at 12563.46,3867.6 h60
  text "X" at 12956.46,3867.6 h60
  text "BOTTOM" at 13074.46,3867.6 h60
  text "SILKSCREEN COLOR:" at 11488.68,3712.41 h60
  text "X" at 12445.46,3712.41 h60
  text "WHITE" at 12563.46,3712.41 h60
  text "OTHER" at 13074.46,3712.41 h60
  text "X" at 12576.46,3568.96 h60
  text "BLUE" at 12694.46,3568.96 h60
  text "OTHER" at 13312.46,3568.96 h60
  text "SOLDER RESIST COLOR:" at 11488.68,3562.1 h60
  text "X" at 12576.46,3414.71 h60
  text "MATTE" at 12694.46,3414.71 h60
  text "SEMI-GLOSS" at 13312,3414.07 h60
  text "IMMERSION GOLD (ENIG)" at 12394.46,3241.94 h60
  text "ENEPIG" at 13732,3234.72 h60
  text "SURFACE FINISH:" at 11333.46,3233.72 h60
  text "X" at 12216.46,3233.72 h60
  text "IMM. TIN/SILVER OR EQUIV" at 11663,3096.4 h60
  text "OTHER" at 13094.46,3092.47 h60
  text "ARRAY/PANEL:" at 11333.46,2937.09 h60
  text "CUT AND TRIM PER M1 BOARD OUTLINE" at 12394.46,2928.87 h60
  text "N.C. ROUTE" at 12394.46,2792.9 h60
  text "X" at 13082.46,2792.9 h60
  text "V. SCORE" at 13260.46,2792.9 h60
  text "CERTIFICATION:" at 11333.46,2663.77 h60
  text "MATERIALS AND WORKMANSHIP FOR ALL PCBS" at 12058.46,2663.77 h60
  text "TO MEET OR EXCEED THE REQUIREMENTS OF:" at 12058.46,2569.71 h60
  text "X" at 11695.97,2441.08 h60
  text "ANSI IPC-A-600F CLASS ->" at 11823.96,2441.08 h60
  text "X" at 13471.97,2441.08 h60
  text "2" at 13581.96,2441.08 h60
  text "1" at 13266.96,2439.58 h60
  text "3" at 13935.96,2439.58 h60
  text "X" at 12507.97,2293.39 h60
  text "RoHS" at 12635.96,2293.39 h60
  text "OTHER" at 13280.36,2293.39 h60
  text "PER ORDER" at 13677.42,2293.39 h60
  text "ALL BOARDS MUST MEET OR EXCEED UL94-V0 REQUIREMENTS." at 11361,2139.57 h60
  text "PCB MUST BEAR THE UL94V-0 UL REGISTERED MATERIAL ID NUMBER" at 11361,2023.5 h60
  text "ADDITIONAL REQUIREMENTS:" at 11333.46,1854.08 h60
  text "MICROSECTION:" at 11408.23,1746.95 h60
  text "YES" at 12313.96,1746.95 h60
  text "REQUIRED" at 13175.46,1602.62 h60
  text "BARE BOARD ELEC. TEST:" at 11408.23,1599.76 h60
  text "NONE" at 12713.96,1599.76 h60
  text "X" at 13057.46,1599.76 h60
  text "PER ORDER" at 13767.46,1599.76 h60
  text "XX MIL VIAS REQUIRE NON-CONDUCTIVE FILL AND PLANARIZE" at 11576.38,1394.82 h59
  text "XX MIL VIAS REQUIRE CONDUCTIVE FILL AND PLANARIZE" at 11584.38,1290.84 h60
  text "OUTER XX MIL TRACES REQUIRE 50 OHM SINGLE-ENDED IMPEDANCE" at 11583.39,1127.46 h58
  text "LAYER 2 & 3 (INNER LAYERS) XX MIL WIDE, XX MIL SPACE / TRACES REQUIRE 100 OHM DIFFERENTIAL IMPEDANCE" at 11575.39,891.74 h60
  text ".Layer_Name" at 577,-858.49 h60
M11 Gerber Information:
  lines w10: -292,-930.17 6308,-930.17 ; -292,-726.83 6310,-726.83 ; -292,-523.5 -292,-1133.5 3713,-1133.5 6310,-1133.5 6310,-523.5 -291.5,-523.5 -291.5,-1133.5 1284,-1133.5 ; 2173,-1133.5 2173,-523.5 ; 3440,-726.83 3440,-523.5 ; 4280,-726.83 4280,-523.5 ; 4902,-1140 4902,-937.17
  text "ALL ARTWORK VIEWED FROM TOP SIDE" at -228.5,-655.67 h60
  text "BOARD #:" at 2248,-655.67 h60
  text ".PRJ_Number" at 2793.5,-655.67 h60
  text "REV:" at 3638,-655.67 h60
  text ".PCB_Rev" at 3929.5,-655.67 h60
  text "SVN REV:" at 4476,-655.67 h60
  text ".VersionControl_RevNumber" at 4982,-655.67 h60
  text "LAYER NAME =" at -228.5,-858.49 h60
  text "TID #:" at 2248,-859 h60
  text ".TID" at 2793.5,-859 h60
  text "PLOT NAME =" at -228.5,-1064.34 h60
  text ".plot_File_Name" at 577,-1064.34 h60
  text "GENERATED    :" at 2250,-1064.34 h60
  text ".Print_Date" at 3119.5,-1064.34 h60
  text ".Print_Time" at 3848.5,-1064.34 h60
  text "TEXAS INSTRUMENTS" at 5113,-1064.34 h60
M12 Stackup:
  drawing of 295 lines, arcs and shapes, not listed
  text "Layer" at 6156.85,4733.5 h60
  text "Name" at 6566.77,4733.5 h60
  text "Material" at 7526.5,4733.5 h60
  text "Thickness" at 8386.27,4733.5 h60
  text "Constant" at 9036.1,4733.5 h60
  text "Board Layer Stack" at 9605.96,4733.5 h60
  text "Top Overlay" at 6566.77,4613.5 h60
  text "Top Solder" at 6566.77,4493.5 h60
  text "Solder Resist" at 7526.5,4493.5 h60
  text "0.40mil" at 8386.27,4493.5 h60
  text "3.5" at 9036.1,4493.5 h60
  text "1" at 6156.85,4373.5 h60
  text "Top Layer" at 6566.77,4373.5 h60
  text "2.74mil" at 8386.27,4373.5 h60
  text "Dielectric 1" at 6566.77,4253.5 h60
  text "FR-4" at 7526.5,4253.5 h60
  text "25.00mil" at 8386.27,4253.5 h60
  text "4.2" at 9036.1,4253.5 h60
  text "2" at 6156.85,4133.5 h60
  text "GND" at 6566.77,4133.5 h60
  text "1.40mil" at 8386.27,4133.5 h60
  text "Dielectric1" at 6566.77,4013.5 h60
  text "FR-4" at 7526.5,4013.5 h60
  text "21.00mil" at 8386.27,4013.5 h60
  text "4.2" at 9036.1,4013.5 h60
  text "3" at 6156.85,3893.5 h60
  text "Copper Layer 3" at 6566.77,3893.5 h60
  text "1.40mil" at 8386.27,3893.5 h60
  text "Dielectric 3" at 6566.77,3773.5 h60
  text "FR-4" at 7526.5,3773.5 h60
  text "25.00mil" at 8386.27,3773.5 h60
  text "4.2" at 9036.1,3773.5 h60
  text "4" at 6156.85,3653.5 h60
  text "Bottom Layer" at 6566.77,3653.5 h60
  text "2.74mil" at 8386.27,3653.5 h60
  text "Bottom Solder" at 6566.77,3533.5 h60
  text "Solder Resist" at 7526.5,3533.5 h60
  text "0.40mil" at 8386.27,3533.5 h60
  text "3.5" at 9036.1,3533.5 h60
  text "Bottom Overlay" at 6566.77,3413.5 h60
  text ".Layer_Name" at 577,-858.49 h60
M13 Component Bodies Top:
  text ".Layer_Name" at 577,-858.49 h60
M14 Component Bodies Bottom:
  text ".Layer_Name" at 577,-858.49 h60
M15 Courtyards Top:
  text ".Layer_Name" at 577,-858.49 h60
M16 Courtyards Bottom:
  text ".Layer_Name" at 577,-858.49 h60
Drill Drawing:
  drawing of 167 lines, arcs and shapes, not listed
  text "Symbol" at 5992.03,3198.01 h51.02
  text "Count" at 6359.85,3198.01 h51.02
  text "Hole Size" at 6826.19,3198.01 h51.02
  text "Plated" at 7646.76,3198.01 h51.02
  text "Hole Type" at 8014.58,3198.01 h51.02
  text "Drill Layer Pair" at 8543.93,3198.01 h51.02
  text "Via/Pad" at 9612.46,3198.01 h51.02
  text "Hole Tolerance" at 10039.79,3198.01 h51.02
  text "2" at 6359.85,3091.71 h42.52
  text "23.62mil (0.600mm)" at 6826.19,3091.71 h42.52
  text "PTH" at 7646.76,3091.71 h42.52
  text "Slot" at 8014.58,3091.71 h42.52
  text "Top Layer - Bottom Layer" at 8543.93,3091.71 h42.52
  text "Pad" at 9612.46,3091.71 h42.52
  text "2" at 6359.85,2985.41 h42.52
  text "27.56mil (0.700mm)" at 6826.19,2985.41 h42.52
  text "PTH" at 7646.76,2985.41 h42.52
  text "Slot" at 8014.58,2985.41 h42.52
  text "Top Layer - Bottom Layer" at 8543.93,2985.41 h42.52
  text "Pad" at 9612.46,2985.41 h42.52
  text "2" at 6359.85,2879.11 h42.52
  text "63.00mil (1.600mm)" at 6826.19,2879.11 h42.52
  text "NPTH" at 7646.76,2879.11 h42.52
  text "Round" at 8014.58,2879.11 h42.52
  text "Top Layer - Bottom Layer" at 8543.93,2879.11 h42.52
  text "Pad" at 9612.46,2879.11 h42.52
  text "2" at 6359.85,2772.81 h42.52
  text "66.93mil (1.700mm)" at 6826.19,2772.81 h42.52
  text "NPTH" at 7646.76,2772.81 h42.52
  text "Round" at 8014.58,2772.81 h42.52
  text "Top Layer - Bottom Layer" at 8543.93,2772.81 h42.52
  text "Pad" at 9612.46,2772.81 h42.52
  text "2" at 6359.85,2666.51 h42.52
  text "118.11mil (3.000mm)" at 6826.19,2666.51 h42.52
  text "PTH" at 7646.76,2666.51 h42.52
  text "Round" at 8014.58,2666.51 h42.52
  text "Top Layer - Bottom Layer" at 8543.93,2666.51 h42.52
  text "Pad" at 9612.46,2666.51 h42.52
  text "A" at 5969.41,2656.51 h47.24
  text "3" at 6359.85,2560.21 h42.52
  text "52.00mil (1.321mm)" at 6826.19,2560.21 h42.52
  text "PTH" at 7646.76,2560.21 h42.52
  text "Round" at 8014.58,2560.21 h42.52
  text "Top Layer - Bottom Layer" at 8543.93,2560.21 h42.52
  text "Pad" at 9612.46,2560.21 h42.52
  text "4" at 6359.85,2453.9 h42.52
  text "43.31mil (1.100mm)" at 6826.19,2453.9 h42.52
  text "PTH" at 7646.76,2453.9 h42.52
  text "Round" at 8014.58,2453.9 h42.52
  text "Top Layer - Bottom Layer" at 8543.93,2453.9 h42.52
  text "Pad" at 9612.46,2453.9 h42.52
  text "4" at 6359.85,2347.6 h42.52
  text "63.00mil (1.600mm)" at 6826.19,2347.6 h42.52
  text "PTH" at 7646.76,2347.6 h42.52
  text "Round" at 8014.58,2347.6 h42.52
  text "Top Layer - Bottom Layer" at 8543.93,2347.6 h42.52
  text "Pad" at 9612.46,2347.6 h42.52
  text "4" at 6359.85,2241.3 h42.52
  text "70.00mil (1.778mm)" at 6826.19,2241.3 h42.52
  text "PTH" at 7646.76,2241.3 h42.52
  text "Round" at 8014.58,2241.3 h42.52
  text "Top Layer - Bottom Layer" at 8543.93,2241.3 h42.52
  text "Pad" at 9612.46,2241.3 h42.52
  text "4" at 6359.85,2135 h42.52
  text "141.73mil (3.600mm)" at 6826.19,2135 h42.52
  text "PTH" at 7646.76,2135 h42.52
  text "Round" at 8014.58,2135 h42.52
  text "Top Layer - Bottom Layer" at 8543.93,2135 h42.52
  text "Pad" at 9612.46,2135 h42.52
  text "4" at 6359.85,2028.7 h42.52
  text "144.00mil (3.658mm)" at 6826.19,2028.7 h42.52
  text "PTH" at 7646.76,2028.7 h42.52
  text "Round" at 8014.58,2028.7 h42.52
  text "Top Layer - Bottom Layer" at 8543.93,2028.7 h42.52
  text "Pad" at 9612.46,2028.7 h42.52
  text "6" at 6359.85,1922.4 h42.52
  text "10.00mil (0.254mm)" at 6826.19,1922.4 h42.52
  text "PTH" at 7646.76,1922.4 h42.52
  text "Round" at 8014.58,1922.4 h42.52
  text "Top Layer - Bottom Layer" at 8543.93,1922.4 h42.52
  text "Via" at 9612.46,1922.4 h42.52
  text "B" at 5969.41,1912.4 h47.24
  text "6" at 6359.85,1816.1 h42.52
  text "24.00mil (0.610mm)" at 6826.19,1816.1 h42.52
  text "PTH" at 7646.76,1816.1 h42.52
  text "Round" at 8014.58,1816.1 h42.52
  text "Top Layer - Bottom Layer" at 8543.93,1816.1 h42.52
  text "Pad" at 9612.46,1816.1 h42.52
  text "6" at 6359.85,1709.79 h42.52
  text "31.50mil (0.800mm)" at 6826.19,1709.79 h42.52
  text "PTH" at 7646.76,1709.79 h42.52
  text "Round" at 8014.58,1709.79 h42.52
  text "Top Layer - Bottom Layer" at 8543.93,1709.79 h42.52
  text "Pad" at 9612.46,1709.79 h42.52
  text "G" at 5969.41,1699.8 h47.24
  text "7" at 6359.85,1603.49 h42.52
  text "7.87mil (0.200mm)" at 6826.19,1603.49 h42.52
  text "PTH" at 7646.76,1603.49 h42.52
  text "Round" at 8014.58,1603.49 h42.52
  text "Top Layer - Bottom Layer" at 8543.93,1603.49 h42.52
  text "Via" at 9612.46,1603.49 h42.52
  text "E" at 5969.41,1593.5 h47.24
  text "10" at 6359.85,1497.19 h42.52
  text "35.43mil (0.900mm)" at 6826.19,1497.19 h42.52
  text "PTH" at 7646.76,1497.19 h42.52
  text "Round" at 8014.58,1497.19 h42.52
  text "Top Layer - Bottom Layer" at 8543.93,1497.19 h42.52
  text "Pad" at 9612.46,1497.19 h42.52
  text "F" at 5969.41,1487.2 h47.24
  text "12" at 6359.85,1390.89 h42.52
  text "11.81mil (0.300mm)" at 6826.19,1390.89 h42.52
  text "PTH" at 7646.76,1390.89 h42.52
  text "Round" at 8014.58,1390.89 h42.52
  text "Top Layer - Bottom Layer" at 8543.93,1390.89 h42.52
  text "Via" at 9612.46,1390.89 h42.52
  text "D" at 5969.41,1380.9 h47.24
  text "59" at 6359.85,1284.59 h42.52
  text "40.00mil (1.016mm)" at 6826.19,1284.59 h42.52
  text "PTH" at 7646.76,1284.59 h42.52
  text "Round" at 8014.58,1284.59 h42.52
  text "Top Layer - Bottom Layer" at 8543.93,1284.59 h42.52
  text "Pad" at 9612.46,1284.59 h42.52
  text "1386" at 6359.85,1178.29 h42.52
  text "10.00mil (0.254mm)" at 6826.19,1178.29 h42.52
  text "PTH" at 7646.76,1178.29 h42.52
  text "Round" at 8014.58,1178.29 h42.52
  text "Top Layer - Bottom Layer" at 8543.93,1178.29 h42.52
  text "Via" at 9612.46,1178.29 h42.52
  text "+/-3.00mil" at 10039.79,1178.29 h42.52
  text "C" at 5969.41,1168.3 h47.24
  text "1525 Total" at 6359.85,1071.99 h42.52
  text "Slot definitions :" at 5992.03,963.42 h42.52
  text "Routed Path Length" at 6732.03,963.42 h42.52
  text "= Calculated from tool start centre position to tool end centre position." at 7521.62,963.42 h42.52
  text "Hole Length" at 6732.03,886.74 h42.52
  text "= Routed Path Length + Tool Size = Slot length as defined in the PCB layout" at 7231.15,886.74 h42.52
  text ".Layer_Name" at 577,-858.49 h60
M17 Embedded Cavity:
  text ".Layer_Name" at 577,-858.49 h60
M18 Embedded Assembly:
  text ".Layer_Name" at 577,-858.49 h60
M19 Embedded Keepout:
  text ".Layer_Name" at 577,-858.49 h60

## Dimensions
0,0 to 0,4803.15 on M2 Board Dimensions
0,-400 to 1000,-400 on M2 Board Dimensions
0,0 to 5314.96,0 on M2 Board Dimensions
